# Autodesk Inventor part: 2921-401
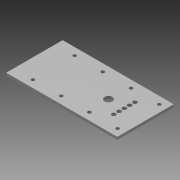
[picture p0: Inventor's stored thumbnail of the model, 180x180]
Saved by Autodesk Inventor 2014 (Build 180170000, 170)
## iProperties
Company: NHTSA/VRTC
Created: 2012-08
Part Number: 2921-401
Material: Steel
Document SubType Name: Modeling
Designer: Mike Vanvoorhis
Density: 7.85 g/cm^3
Mass: 5886.92 g
Surface Area: 1751.26 cm^2
Volume: 749.927 cm^3
Description: ANTI-REBOUND FIXTURE BASE PLATE
Project: CHILD SIDE IMPACT SLED
Stock Number: PL 9.5 (3/8") x 203.2 (8") x 400.1 (15 3/4")
Appearance: Steel
DESIGN DATE: 2012-11-05
Author: Dave Walker
Title: Anti-Rebound Fixture Base Plate
Subject: Child Sid Impact Sled
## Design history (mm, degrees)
sketch "Sketch1"
  geometry: L1 (0, 0)-(400.05, 0); L2 (400.05, 0)-(400.05, -9.525); L3 (400.05, -9.525)-(0, -9.525); L4 (0, -9.525)-(0, 0)
  constraints: 8 end point, 2 parallel, 1 horizontal, 1 perpendicular
  dimensions: "d0" = 400.05 distance of L2.end L3.end; "d1" = 9.525 distance of L1.end L2.end
extrude "Extrusion1" new body sketch "Sketch1" distance "d2" = 203.2; taper "d3" = 0 deg
sketch "Sketch2"
  geometry: L1 (0, 0)-(0, 203.2) reference; L2 (400.05, 0)-(400.05, 203.2) reference; L3 (0, 101.6)-(400.05, 101.6); C1 r 6.35 at (69.85, 26.543); C2 r 6.35 at (171.45, 26.543); C3 r 6.35 at (273.05, 26.543); C4 r 6.35 at (374.65, 26.543); C5 r 6.35 at (374.65, 176.657); C6 r 6.35 at (273.05, 176.657); C7 r 6.35 at (171.45, 176.657); C8 r 6.35 at (69.85, 176.657)
  constraints: 8 centre point, 6 horizontal alignment, 4 vertical alignment, 2 end point, 2 midpoint
  dimensions: "d12" = 12.7 diameter of C1; "d20" = 25.4 horizontal distance of L2.start C4.centre; "d22" = 127 horizontal distance of L2.start C3.centre; "d24" = 228.6 horizontal distance of L2.start C2.centre; "d25" = 330.2 horizontal distance of L2.start C1.centre; "d103" = 150.114 distance of C1.centre C8.centre; "d104" = 75.057 distance from line of C1.centre L3 (= 0.5 x d103); "d105" = 12.7 diameter of C2 (= d12); "d106" = 12.7 diameter of C3 (= d12); "d107" = 12.7 diameter of C4 (= d12); "d108" = 12.7 diameter of C8 (= d12); "d109" = 12.7 diameter of C7 (= d12); "d110" = 12.7 diameter of C6 (= d12); "d111" = 12.7 diameter of C5 (= d12)
hole "Hole1" sketch "Sketch2" at (69.85, 26.543), (69.85, 176.657), (171.45, 176.657), (273.05, 176.657), (374.65, 176.657), (374.65, 26.543), (273.05, 26.543), (171.45, 26.543) diameter "d13" = 12.7; stored, may be unused: countersink angle "d17" = 82 deg, drill point angle "d19" = 118 deg; dims "d14" = 19.05, "d15" = 9.525, "d16" = 6.35, "d18" = 25.4
sketch "Sketch3"
  geometry: L1 (400.05, 0)-(400.05, 203.2) reference; L2 (323.85, 139.7)-(323.85, 120.65); L3 (323.85, 120.65)-(323.85, 101.6); L4 (323.85, 101.6)-(323.85, 82.55); L5 (400.05, 203.2)-(0, 203.2) reference; L6 (0, 0)-(0, 203.2) reference; L7 (0, 0)-(400.05, 0) reference; L8 (400.05, 0)-(400.05, 203.2) reference; C1 r 7.62 at (323.85, 139.7); C2 r 7.62 at (323.85, 63.5); C3 r 7.62 at (323.85, 120.65); C4 r 7.62 at (323.85, 101.6); C5 r 7.62 at (323.85, 82.55); C6 r 6.35 at (171.45, 26.543) reference; C7 r 6.35 at (273.05, 26.543) reference; C8 r 6.35 at (374.65, 26.543) reference; C9 r 6.35 at (374.65, 176.657) reference; C10 r 6.35 at (273.05, 176.657) reference; C11 r 6.35 at (171.45, 176.657) reference; C12 r 6.35 at (69.85, 176.657) reference; C13 r 6.35 at (69.85, 26.543) reference
  constraints: 6 end point, 5 centre point, 3 coincident, 2 collinear, 1 parallel
  dimensions: "d85" = 19.05 distance of L2.start L2.end; "d86" = 19.05 distance of L2.end L3.end; "d87" = 19.05 distance of L3.end L4.end; "d88" = 76.2 horizontal distance of L4.end L1.start; "d89" = 19.05 distance of L3.end C5.centre (derived)
hole "Hole2" sketch "Sketch3" at (323.85, 139.7), (323.85, 63.5) diameter "d56" = 15.24; stored, may be unused: countersink angle "d60" = 82 deg, drill point angle "d62" = 118 deg; dims "d57" = 19.05, "d58" = 9.525, "d59" = 6.35, "d61" = 6.35
sketch "Sketch5"
  geometry: C1 r 9.525 at (266.7, 101.6); 1 further point
  constraints: 1 centre point
  dimensions: "d75" = 19.05 diameter of C1; "d76" = 133.35 horizontal distance of point (400.05, 0) C1.centre; "d77" = 101.6 vertical distance of C1.centre point (400.05, 0)
hole "Hole4" sketch "Sketch5" at (266.7, 101.6) diameter "d78" = 28.3718; stored, may be unused: countersink angle "d82" = 82 deg, drill point angle "d84" = 118 deg; dims "d79" = 19.05, "d80" = 9.525, "d81" = 6.35, "d83" = 25.4
sketch "Sketch7"
  geometry: L1 (400.05, 0)-(400.05, 203.2) reference; L2 (323.85, 63.5)-(323.85, 82.55); L3 (323.85, 82.55)-(323.85, 101.6); L4 (323.85, 101.6)-(323.85, 120.65); C1 r 7.62 at (323.85, 63.5) reference; C2 r 7.62 at (323.85, 120.65); C3 r 7.62 at (323.85, 101.6); C4 r 7.62 at (323.85, 82.55)
  constraints: 6 end point, 3 centre point, 3 coincident, 2 collinear, 1 parallel
  dimensions: "d90" = 19.05 distance of L2.start L2.end; "d91" = 19.05 distance of L2.end L3.end; "d92" = 19.05 distance of L3.end L4.end; "d93" = 15.24 diameter of C2; "d94" = 15.24 diameter of C3; "d95" = 15.24 diameter of C4
hole "Hole5" sketch "Sketch7" at (323.85, 82.55), (323.85, 101.6), (323.85, 120.65) diameter "d96" = 15.24; stored, may be unused: countersink angle "d100" = 82 deg, drill point angle "d102" = 118 deg; dims "d97" = 19.05, "d98" = 9.525, "d99" = 6.35, "d101" = 25.4
body "Solid1"
node "Projected Loop2"
